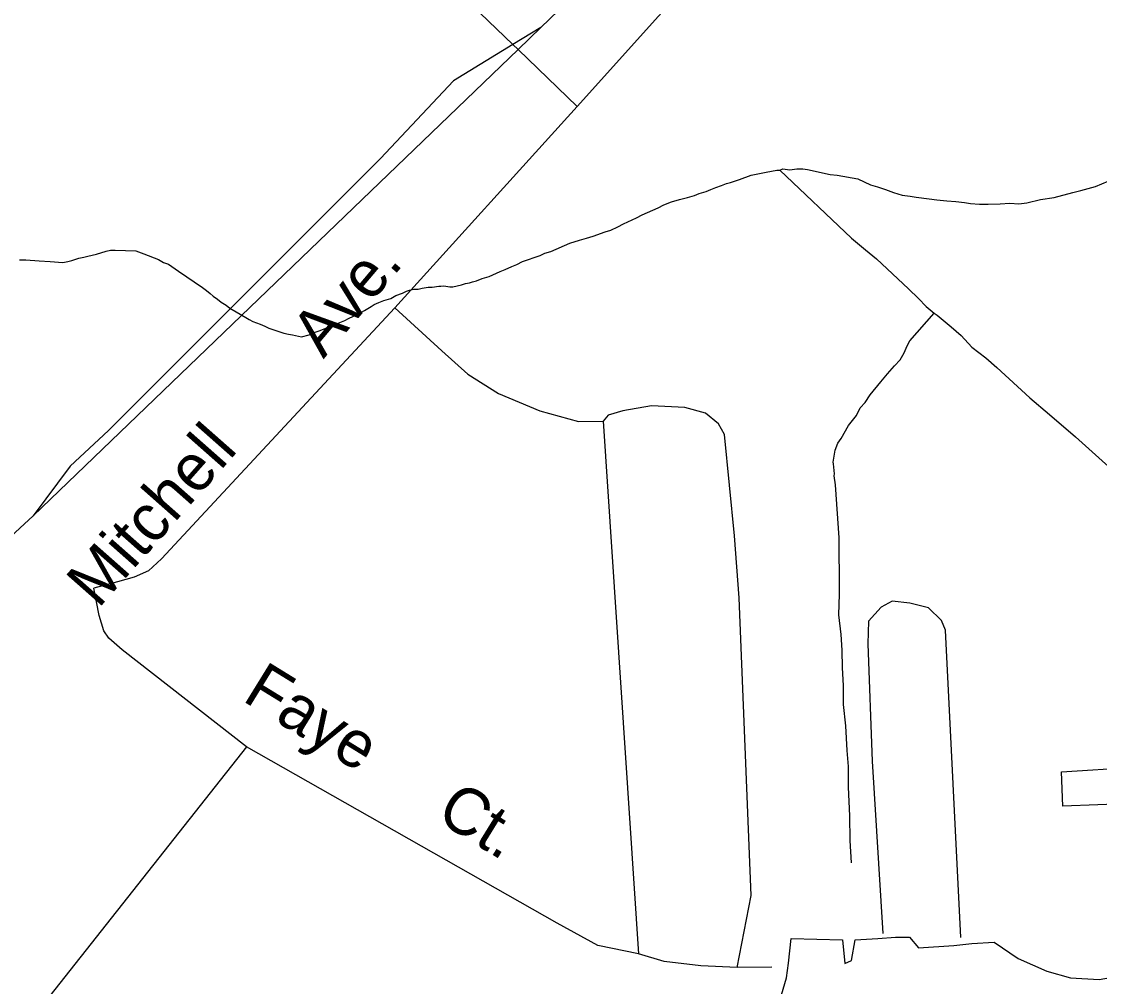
# Model space of a CAD drawing. Extents: x 2260773 to 2342389, y 552869 to 618546.
# Drawn here: x 2304425 to 2306610, y 582302 to 584259 of the extents above; entities that cross this region are included whole.
import ezdxf

# ---------------------------------------------------------------- set-up
doc = ezdxf.new("R2010")
doc.units = 0
for name, color, linetype in [('Exist Aviation Commercial or Municipal Perimeter Paved', 7, 'Continuous'), ('Exist Hydrographic Misc Water Feature', 7, 'Continuous'), ('Exist Railroad Mainline', 7, 'Continuous'), ('Exist Railroad Siding', 7, 'Continuous'), ('Exist Road Non-System Type 51', 7, 'Continuous'), ('Exist Road Non-System Type 51 Label', 7, 'Continuous')]:
    doc.layers.add(name, color=color, linetype=linetype)

msp = doc.modelspace()

# ---------------------------------------------------------------- linework, layer by layer
at = {"layer": 'Exist Aviation Commercial or Municipal Perimeter Paved'}
for points in [[(2306678, 582673.1), (2306536, 582667.6), (2306533.4, 582737.5), (2306681.2, 582747.1)], [(2305956.7, 582255.5), (2305976.1, 582319.7), (2305979.7, 582349.6), (2305985.3, 582399.7), (2306089.2, 582396.9), (2306093.8, 582348.8), (2306107.7, 582355), (2306115.2, 582397.1), (2306161.1, 582399.6), (2306197, 582402), (2306225, 582402.4), (2306243.3, 582380.5), (2306315.1, 582385.2), (2306351.2, 582389.6), (2306397.1, 582392.1), (2306445.4, 582358.6), (2306503.7, 582333.4), (2306551.8, 582319.9), (2306609.8, 582316.5), (2306659.6, 582325.1)]]:
    msp.add_lwpolyline(points, dxfattribs=at)
at = {"layer": 'Exist Hydrographic Misc Water Feature'}
for points in [[(2305758.8, 583898.4), (2305775.2, 583902.5), (2305789.1, 583906.5), (2305798.8, 583910.7), (2305812.9, 583914.6), (2305822.6, 583918.8), (2305832.6, 583923), (2305844.3, 583926.9), (2305854.4, 583931.1), (2305862.4, 583933.1), (2305880.4, 583939.3), (2305904.4, 583947.9), (2305914.4, 583950), (2305934.3, 583953.9), (2305956.3, 583958.3), (2305962.2, 583958.2)], [(2305962.2, 583958.2), (2305968.6, 583960.5), (2305982.3, 583958.5), (2305996.7, 583960.8), (2306008.6, 583961), (2306018.4, 583959.1), (2306064.5, 583949.3), (2306078.3, 583947.7), (2306120.3, 583940.1), (2306146.3, 583928.5), (2306160.5, 583924.3), (2306176.7, 583918.7), (2306192.7, 583913), (2306210.3, 583907.1), (2306226.7, 583905), (2306238.6, 583903.2), (2306264.9, 583899.7), (2306280.7, 583897.8), (2306300.8, 583895.9), (2306318.8, 583894.4), (2306336.8, 583892.5), (2306348.7, 583890.7), (2306366.8, 583888.8), (2306384.6, 583889), (2306409, 583889.4), (2306428.7, 583891.2), (2306446.7, 583889.8), (2306462.9, 583891.8), (2306490.6, 583898.2), (2306518.7, 583902.5), (2306556.5, 583912.6), (2306572.4, 583917.1), (2306602.4, 583925.1), (2306666.4, 583952)], [(2305962.2, 583958.2), (2306107.6, 583820), (2306135.9, 583796.3), (2306158, 583778.3), (2306223, 583717.4), (2306243.1, 583697.4), (2306259.1, 583681.6), (2306275.1, 583667.8)], [(2304420.8, 583775.8), (2304433.3, 583776), (2304461, 583774.3), (2304483.2, 583772.6), (2304508.8, 583770.7), (2304519.1, 583772.8), (2304527.1, 583774.9), (2304541, 583779.3), (2304551, 583781.4), (2304559, 583783.4), (2304576.7, 583787.7), (2304596.8, 583793.6), (2304605, 583796), (2304614.6, 583795.7), (2304656.8, 583794.3), (2304672.8, 583788.6), (2304702.8, 583776.8), (2304712.8, 583770.8), (2304722.9, 583767.3), (2304743.2, 583753.3), (2304791.6, 583719.7), (2304799.6, 583714), (2304807.4, 583707.9), (2304813.7, 583702.1), (2304822.1, 583696.4), (2304829.9, 583690.3), (2304839.6, 583684.4), (2304847.5, 583678.3), (2304859.9, 583670.8), (2304879.9, 583658.9), (2304886.1, 583655.1), (2304894.1, 583651.1), (2304908.4, 583645.3), (2304918.3, 583641.3), (2304926.1, 583637.3), (2304944.3, 583631.7), (2304956.4, 583627.5), (2304966.3, 583625.6), (2304974.1, 583624.1), (2304992.5, 583620.1), (2305008.1, 583624.2), (2305018.2, 583628.4), (2305030.2, 583632.6), (2305060, 583644.8), (2305080.1, 583653.1), (2305088.1, 583657.2), (2305109.6, 583667.3), (2305120.1, 583673.4), (2305133.6, 583681.5), (2305139.5, 583685.5), (2305149.6, 583689.7), (2305159.6, 583693.8), (2305173.4, 583697.8), (2305183.8, 583704), (2305197.2, 583708.4), (2305205.6, 583712.5), (2305211.5, 583714.4), (2305219.5, 583716.5), (2305229.1, 583716.6), (2305237.1, 583718.6), (2305249, 583720.9), (2305257.4, 583720.8), (2305271, 583722.9), (2305275.3, 583723), (2305281.4, 583723.4), (2305293.3, 583721.2), (2305299.3, 583721.5), (2305316.9, 583725.7), (2305324.9, 583727.8), (2305332.9, 583729.8), (2305339.3, 583731.7), (2305347.3, 583733.7), (2305358.9, 583738), (2305372.9, 583742), (2305395, 583752.5), (2305405.1, 583756.6), (2305418.8, 583762.7), (2305428.9, 583766.8), (2305440.4, 583772.8), (2305452.7, 583777.1), (2305464.3, 583781), (2305476.4, 583785.2), (2305486.1, 583789.4), (2305498.2, 583793.3), (2305536.3, 583809.9), (2305556, 583816.2), (2305570.4, 583820.2), (2305583.7, 583824.2), (2305608.1, 583832.7), (2305619.8, 583836.6), (2305634.1, 583843), (2305645.6, 583848.9), (2305671.4, 583861.3), (2305683.1, 583867.3), (2305715.3, 583881.9), (2305727, 583887.8), (2305742.8, 583894), (2305758.8, 583898.4)], [(2306107.4, 582552.7), (2306104.9, 582598.5), (2306104.3, 582648.5), (2306101.6, 582706.5), (2306101.4, 582748.7), (2306098.6, 582780.7), (2306096.3, 582830.6), (2306091.6, 582874.2), (2306091.6, 582912.4), (2306089.1, 582948.5), (2306088.7, 582984.2), (2306086.3, 583016.2), (2306082, 583056.2), (2306083.4, 583098.2), (2306083.2, 583120), (2306083, 583144), (2306082.4, 583174.1), (2306082.4, 583212.2), (2306075.2, 583320), (2306072.7, 583337.8), (2306072.9, 583341.8), (2306070.9, 583362), (2306070.5, 583365.7), (2306074.2, 583389.9), (2306079.9, 583404), (2306086.3, 583414), (2306101.6, 583440.1), (2306109.6, 583450.2), (2306117.8, 583460.4), (2306125.4, 583476.2), (2306135.3, 583486.5), (2306145.1, 583502.5), (2306167.1, 583528.8), (2306180.8, 583545), (2306194.5, 583561.2), (2306206.2, 583573.2), (2306214.2, 583587.4), (2306220.4, 583601.5), (2306225.9, 583611.6), (2306275.1, 583667.8)], [(2306275.1, 583667.8), (2306281.3, 583664), (2306309.6, 583640.3), (2306329.7, 583622.7), (2306351.6, 583598.7), (2306379.9, 583577.1), (2306402.5, 583557.4), (2306469.3, 583496.3), (2306509.3, 583462.7), (2306562, 583417), (2306682.8, 583308.4), (2306795.7, 583205.8), (2306898.9, 583112.8), (2306911, 583101.3), (2306921.2, 583093.2), (2306931.1, 583083.3), (2306941.1, 583075.2), (2306985.8, 583039.7)]]:
    msp.add_lwpolyline(points, dxfattribs=at)
at = {"layer": 'Exist Railroad Mainline'}
msp.add_line((2304365.1, 583179.9), (2304448.8, 583256.6), dxfattribs=at)
for points in [[(2305477.6, 584247.2), (2305622, 584386.7), (2305809.8, 584586.7), (2306056.9, 584841.1)], [(2304448.8, 583256.6), (2305431.5, 584202.9), (2305477.6, 584247.2)]]:
    msp.add_lwpolyline(points, dxfattribs=at)
at = {"layer": 'Exist Railroad Siding'}
msp.add_lwpolyline([(2305477.6, 584247.2), (2305421.2, 584212.8), (2305300.9, 584139.4), (2305152.6, 583982), (2304601, 583430.2), (2304523.7, 583357.5), (2304448.8, 583256.6)], dxfattribs=at)
at = {"layer": 'Exist Road Non-System Type 51'}
for p, q in [((2305421.2, 584212.8), (2305214.1, 584412.4)), ((2305431.5, 584202.9), (2305421.2, 584212.8)), ((2305551.7, 584087), (2305431.5, 584202.9)), ((2305551.7, 584087), (2305181.7, 583679)), ((2305604.2, 583449.1), (2305675.7, 582368.4)), ((2305945.8, 582341.3), (2305875.9, 582340.6))]:
    msp.add_line(p, q, dxfattribs=at)
for points in [[(2306089.7, 584683.5), (2306040.1, 584631), (2305551.7, 584087)], [(2305181.7, 583679), (2304708.9, 583169.4), (2304682.1, 583145.6), (2304653.1, 583132.6), (2304619.3, 583122.8), (2304571.7, 583110)], [(2305181.7, 583679), (2305276.8, 583591.5), (2305329.4, 583544), (2305391.8, 583504.8), (2305476, 583469.8), (2305554.3, 583448.5), (2305604.2, 583449.1)], [(2305875.9, 582340.6), (2305904.4, 582486.8), (2305879.8, 583090.2), (2305870.5, 583216), (2305850.4, 583421.7), (2305838.1, 583443.6), (2305811.8, 583465.3), (2305769.8, 583476.8), (2305701.8, 583480.1), (2305643.8, 583469.5), (2305614, 583461.1), (2305604.2, 583449.1)], [(2304880.9, 582788.5), (2304628.7, 582985.1), (2304601.9, 583008.9), (2304591.5, 583023.7), (2304582.6, 583055), (2304571.7, 583110)], [(2306329.1, 582401.4), (2306298.3, 583024.7), (2306290.1, 583044.7), (2306263.9, 583070.3), (2306225.9, 583079.9), (2306189.7, 583083.5), (2306167.8, 583071.4), (2306142.1, 583043.2), (2306140.8, 582997.1), (2306149.2, 582759.4), (2306170.9, 582409.8)], [(2304880.9, 582788.5), (2304354.9, 582122.5), (2304297, 582048.9), (2304252.4, 581973.1), (2304220.1, 581898.4)], [(2305675.7, 582368.4), (2305593.6, 582385.5), (2305511.1, 582430.5), (2304880.9, 582788.5)], [(2305875.9, 582340.6), (2305801.9, 582343.9), (2305727.9, 582353.1), (2305675.7, 582368.4)]]:
    msp.add_lwpolyline(points, dxfattribs=at)

# ---------------------------------------------------------------- texts
at = {"layer": 'Exist Road Non-System Type 51 Label'}
for s, rotation, p in [('Ave.', 49.7867, (2305037, 583574.1)), ('Mitchell', 48.5529, (2304580.4, 583067)), ('Faye', 328.3778, (2304870, 582883.1)), ('Ct.', 328.3778, (2305262.1, 582641.6))]:
    msp.add_text(s, height=95, rotation=rotation, dxfattribs=at).set_placement(p)

doc.saveas('drawing.dxf')
